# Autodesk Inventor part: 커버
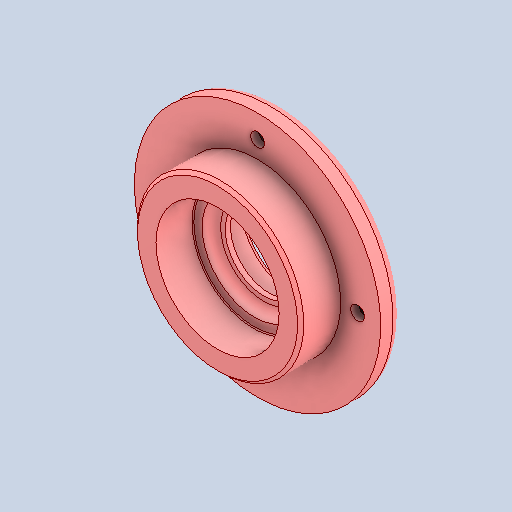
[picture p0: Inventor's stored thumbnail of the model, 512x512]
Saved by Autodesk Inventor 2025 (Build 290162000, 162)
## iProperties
Created: 2026-07
Part Number: 커버
Material: 알루미늄 6061
Document SubType Name: Modeling
Designer: KDI
Density: 2.7 g/cm^3
Appearance: 기본값
Company: 한국ATC센터
Author: jhkim
Revision Number: 1
Sending System: Autodesk Inventor 2027
Preprocessor: ST-DEVELOPER v20.1
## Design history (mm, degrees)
feature "솔리드1"
node "솔리드2"
